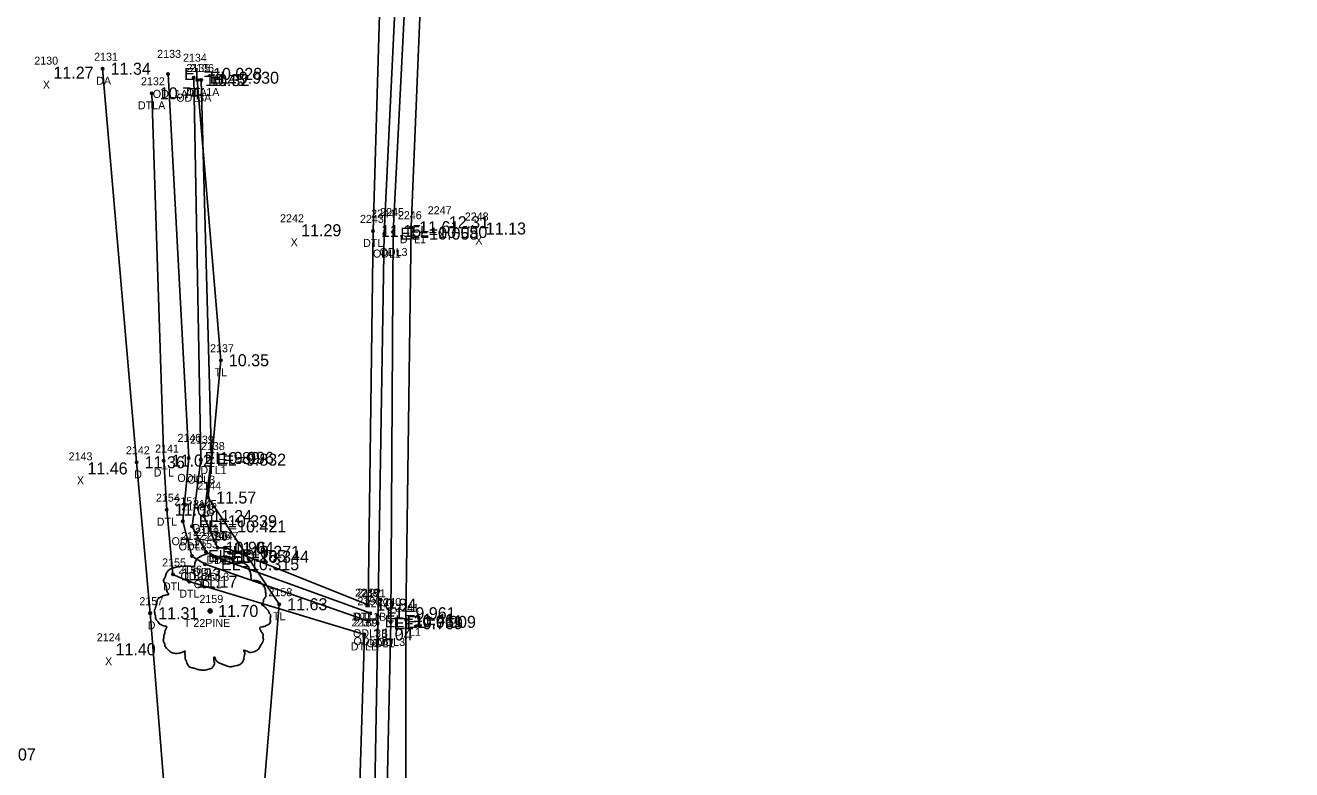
# Model space of a CAD drawing. Extents: x 2042117 to 2045853, y 303080 to 309569.
# Drawn here: x 2044366.1 to 2044524.3, y 304910.7 to 305003.7 of the extents above; entities that cross this region are included whole.
import ezdxf

# ---------------------------------------------------------------- set-up
doc = ezdxf.new("R2010")
doc.units = 0
for name, color, linetype in [('RD_EX_Driveway', 7, 'Continuous'), ('RD_EX_Driveway_txCode', 7, 'Continuous'), ('RD_EX_H2O', 7, 'Continuous'), ('RD_EX_H2O_txCode', 7, 'Continuous'), ('RD_EX_Misc_txCode', 7, 'Continuous'), ('RD_EX_TX_Driveway_ELEV', 7, 'Continuous'), ('RD_EX_TX_H2O_ELEV', 7, 'Continuous'), ('RD_EX_TX_Misc_ELEV', 7, 'Continuous'), ('RD_EX_TX_VEG_ELEV', 7, 'Continuous'), ('RD_EX_VEG', 7, 'Continuous'), ('RD_EX_VEG_txCode', 7, 'Continuous'), ('RD_SMD_Locator', 7, 'Continuous')]:
    doc.layers.add(name, color=color, linetype=linetype)

msp = doc.modelspace()

# ---------------------------------------------------------------- linework, layer by layer
at = {"layer": 'RD_EX_Driveway'}
msp.add_lwpolyline([(2044375.76, 304998.28), (2044380.01, 304949.11), (2044381.7, 304930.26), (2044386.83, 304866.36)], dxfattribs=at)
at = {"layer": 'RD_EX_H2O'}
for points in [[(2044403.47, 304870.69), (2044407.44, 304869.96), (2044408.86, 304871.35), (2044409.24, 304878.26), (2044410.13, 304929), (2044410.94, 304977.69), (2044415.72, 305077.93), (2044415.23, 305082.87), (2044413.63, 305085.18), (2044400.37, 305083.8), (2044376.8, 305083.33)], [(2044412.68, 304824.61), (2044412.4, 304834.83), (2044410.65, 304865.22), (2044410.04, 304868.77), (2044410.66, 304878.11), (2044411.75, 304929.17), (2044412.06, 304977.88), (2044417.16, 305077.8), (2044420.35, 305084.11), (2044441.54, 305085.32)], [(2044415.25, 304826.5), (2044414.68, 304834.74), (2044412.57, 304868.88), (2044413.59, 304878.38), (2044413.66, 304929.44), (2044414.3, 304978.48), (2044418.39, 305077.45), (2044423.01, 305082.15), (2044441.95, 305081.13)], [(2044408.92, 304931.32), (2044409.54, 304978.02), (2044412.44, 305076.31), (2044400.87, 305076.71), (2044383.06, 305073.87), (2044385, 305069.3)], [(2044383.93, 304997.64), (2044386.51, 304949.66), (2044385.78, 304941.75), (2044386.91, 304937.4), (2044388.55, 304936.38), (2044408.98, 304929.26)], [(2044387.15, 304997.16), (2044388.03, 304949.44), (2044386.94, 304941.1), (2044388.67, 304937.92), (2044389.77, 304937.31), (2044409.21, 304930.25)], [(2044388.07, 304996.86), (2044389.38, 304949.64), (2044388.41, 304942.4), (2044390.13, 304938.44), (2044391.11, 304938.42), (2044408.92, 304931.31)], [(2044381.9, 304995.21), (2044383.39, 304949.33), (2044383.77, 304943.19), (2044384.54, 304935.1), (2044386.58, 304934.2), (2044408.47, 304927.6)], [(2044410.56, 304822.99), (2044408.85, 304834.7), (2044407.58, 304865.58), (2044405.53, 304866.37), (2044405.23, 304866.22), (2044401.8, 304866.57), (2044399.35, 304868.17), (2044399.78, 304872.01), (2044401.54, 304873.59), (2044405.93, 304871.59), (2044407.19, 304871.81), (2044406.92, 304878.34), (2044408.47, 304927.6)]]:
    msp.add_lwpolyline(points, dxfattribs=at)
at = {"layer": 'RD_EX_VEG'}
msp.add_lwpolyline([(2044387.58, 304996.88), (2044390.53, 304961.86), (2044388.93, 304944.71), (2044397.82, 304931.38), (2044395.87, 304907.56), (2044407.42, 304883.17), (2044412.64, 304877.39), (2044413.34, 304846.91), (2044417.62, 304826.21), (2044417.53, 304827.99), (2044425.41, 304820.87), (2044430.68, 304811.06), (2044486.4, 304757.95), (2044546.53, 304677.07), (2044611.02, 304596.16), (2044662.5, 304521.9), (2044713.91, 304454.08), (2044725.96, 304441.86), (2044733.75, 304433.55)], dxfattribs=at)
for centre, radius in [((2044389.19, 304930.54), 0.25), ((2044389.18, 304930.52), 0.0001)]:
    msp.add_circle(centre, radius, dxfattribs=at)
for points in [[(2044389.32, 304937.71), (2044389.02, 304937.73), (2044388.7, 304937.63), (2044388.45, 304937.53), (2044388.23, 304937.46), (2044388, 304937.36), (2044387.7, 304937.18), (2044387.48, 304936.98), (2044387.35, 304936.73), (2044387.3, 304936.51), (2044387.25, 304936.23), (2044387.25, 304936.06), (2044387.13, 304936.03), (2044386.98, 304936.06), (2044386.73, 304936.13), (2044386.48, 304936.13), (2044386.23, 304936.13), (2044385.88, 304936.11), (2044385.53, 304936.11), (2044385.25, 304936.06), (2044384.93, 304936.01), (2044384.55, 304935.88), (2044384.2, 304935.76), (2044383.9, 304935.51), (2044383.65, 304935.03), (2044383.53, 304934.68), (2044383.38, 304934.44), (2044383.53, 304933.99), (2044383.7, 304933.64), (2044383.73, 304933.44), (2044383.8, 304933.01), (2044383.9, 304932.79), (2044384.03, 304932.59), (2044383.95, 304932.56), (2044383.58, 304932.51), (2044383.28, 304932.41), (2044382.85, 304932.19), (2044382.63, 304931.96), (2044382.53, 304931.64), (2044382.5, 304931.29), (2044382.4, 304931.09), (2044382.33, 304930.81), (2044382.3, 304930.74), (2044382.25, 304930.41), (2044382.35, 304929.96), (2044382.38, 304929.61), (2044382.5, 304929.39), (2044382.65, 304929.21), (2044382.83, 304928.96), (2044383.23, 304928.74), (2044383.55, 304928.64), (2044383.75, 304928.61), (2044383.58, 304928.11), (2044383.53, 304927.76), (2044383.4, 304927.36), (2044383.4, 304927.29), (2044383.35, 304926.81), (2044383.5, 304926.49), (2044383.58, 304926.11), (2044383.75, 304925.89), (2044384.03, 304925.59), (2044384.35, 304925.36), (2044384.85, 304925.24), (2044385.25, 304925.26), (2044385.83, 304925.44), (2044386.08, 304925.51), (2044386.05, 304925.34), (2044386.08, 304924.96), (2044386.08, 304924.54), (2044386.23, 304924.21), (2044386.33, 304923.94), (2044386.48, 304923.69), (2044386.8, 304923.46), (2044387.2, 304923.39), (2044387.63, 304923.24), (2044388.08, 304923.16), (2044388.58, 304923.14), (2044389.17, 304923.29), (2044389.45, 304923.41), (2044389.55, 304923.59), (2044389.75, 304923.96), (2044389.7, 304924.19), (2044389.72, 304924.79), (2044389.82, 304924.61), (2044390, 304924.26), (2044390.5, 304923.96), (2044390.9, 304923.79), (2044391.37, 304923.64), (2044391.67, 304923.56), (2044392.15, 304923.64), (2044392.52, 304923.71), (2044392.9, 304923.84), (2044393.2, 304924.11), (2044393.37, 304924.39), (2044393.42, 304924.66), (2044393.5, 304925.04), (2044393.55, 304925.21)], [(2044393.55, 304925.21), (2044393.47, 304925.39), (2044393.42, 304925.64), (2044393.5, 304925.61), (2044393.67, 304925.56), (2044393.95, 304925.44), (2044394.17, 304925.36), (2044394.5, 304925.39), (2044394.77, 304925.49), (2044395.22, 304925.76), (2044395.5, 304926.24), (2044395.77, 304926.64), (2044395.85, 304926.96), (2044395.8, 304927.19), (2044395.77, 304927.69), (2044395.57, 304927.94), (2044395.52, 304928.06), (2044395.42, 304928.46), (2044395.5, 304928.51), (2044395.77, 304928.56), (2044396.15, 304928.69), (2044396.42, 304928.81), (2044396.65, 304928.99), (2044396.72, 304929.21), (2044396.7, 304929.61), (2044396.75, 304930.01), (2044396.67, 304930.16), (2044396.57, 304930.31), (2044396.5, 304930.51), (2044396.35, 304930.66), (2044396.25, 304930.81), (2044396.15, 304930.91), (2044396.02, 304931.06), (2044395.85, 304931.19), (2044395.7, 304931.24), (2044395.65, 304931.39), (2044395.8, 304931.59), (2044395.85, 304931.69), (2044395.87, 304931.91), (2044396.1, 304932.26), (2044396.15, 304932.66), (2044396.1, 304933.09), (2044396.05, 304933.36), (2044395.9, 304933.64), (2044395.7, 304933.89), (2044395.57, 304934.06), (2044395.4, 304934.19), (2044395.07, 304934.31), (2044394.82, 304934.36), (2044394.47, 304934.36), (2044394.27, 304934.41), (2044394.3, 304934.46), (2044394.3, 304934.61), (2044394.3, 304934.88), (2044394.22, 304935.33), (2044394.07, 304935.83), (2044394.07, 304935.86), (2044393.97, 304936.11), (2044393.75, 304936.31), (2044393.57, 304936.41), (2044393.37, 304936.53), (2044393.12, 304936.56), (2044392.82, 304936.56), (2044392.55, 304936.51), (2044392.35, 304936.41), (2044392.17, 304936.28), (2044392.1, 304936.43), (2044392, 304936.73), (2044391.95, 304936.88), (2044391.8, 304937.06), (2044391.57, 304937.26), (2044391.12, 304937.38), (2044390.5, 304937.31), (2044390.2, 304937.11), (2044390.05, 304936.93), (2044390, 304937.06), (2044389.8, 304937.26), (2044389.7, 304937.43), (2044389.52, 304937.56), (2044389.37, 304937.66), (2044389.27, 304937.71)]]:
    msp.add_spline(points, degree=3, dxfattribs=at)
at = {"layer": 'RD_SMD_Locator'}
for centre in [(2044375.76, 304998.28), (2044383.93, 304997.64), (2044387.15, 304997.16), (2044387.58, 304996.88), (2044388.07, 304996.86), (2044381.9, 304995.21), (2044409.54, 304978.02), (2044410.94, 304977.69), (2044412.06, 304977.88), (2044414.3, 304978.48), (2044390.53, 304961.86), (2044380.01, 304949.11), (2044383.39, 304949.33), (2044386.51, 304949.66), (2044388.03, 304949.44), (2044389.38, 304949.64), (2044388.93, 304944.71), (2044383.77, 304943.19), (2044388.41, 304942.4), (2044385.78, 304941.75), (2044386.94, 304941.1), (2044388.67, 304937.92), (2044390.13, 304938.44), (2044391.11, 304938.42), (2044386.91, 304937.4), (2044388.55, 304936.38), (2044389.77, 304937.31), (2044384.54, 304935.1), (2044386.58, 304934.2), (2044397.82, 304931.38), (2044408.92, 304931.32), (2044408.92, 304931.31), (2044381.7, 304930.26), (2044389.19, 304930.54), (2044409.21, 304930.25), (2044408.98, 304929.26), (2044410.13, 304929), (2044411.75, 304929.17), (2044413.66, 304929.44), (2044408.47, 304927.6), (2044408.47, 304927.6)]:
    msp.add_circle(centre, 0.15, dxfattribs=at)

# ---------------------------------------------------------------- texts
at = {"layer": 'RD_EX_Driveway_txCode'}
for s, p in [('2131', (2044374.7, 304999.28)), ('DA', (2044374.96, 304996.28)), ('2142', (2044378.67, 304950.11)), ('D', (2044379.71, 304947.11)), ('2157', (2044380.35, 304931.26)), ('D', (2044381.39, 304928.26))]:
    msp.add_text(s, height=1, dxfattribs=at).set_placement(p)
at = {"layer": 'RD_EX_H2O_txCode'}
for s, p in [('2133', (2044382.58, 304999.64)), ('2134', (2044385.8, 304999.16)), ('2136', (2044386.7, 304997.86)), ('2132', (2044380.55, 304996.21)), ('ODL1A', (2044382.03, 304994.64)), ('ODL3A', (2044384.96, 304994.16)), ('DTL1A', (2044386.18, 304994.86)), ('DTLA', (2044380.17, 304993.21)), ('2244', (2044409.31, 304979.69)), ('2245', (2044410.43, 304979.88)), ('2246', (2044412.65, 304979.48)), ('2243', (2044407.91, 304979.02)), ('DTL1', (2044412.89, 304976.48)), ('DTL', (2044408.3, 304976.02)), ('ODL1', (2044409.53, 304974.69)), ('ODL3', (2044410.36, 304974.88)), ('2140', (2044385.12, 304951.66)), ('2139', (2044386.68, 304951.44)), ('2141', (2044382.32, 304950.33)), ('2138', (2044388.04, 304950.64)), ('DTL', (2044382.14, 304947.33)), ('ODL1', (2044385.1, 304946.66)), ('ODL3', (2044386.33, 304946.44)), ('DTL1', (2044387.97, 304947.64)), ('2154', (2044382.42, 304944.19)), ('2151', (2044384.72, 304943.75)), ('2148', (2044385.59, 304943.1)), ('2145', (2044387.06, 304943.4)), ('DTL', (2044382.52, 304941.19)), ('DTL1', (2044387, 304940.4)), ('2149', (2044387.32, 304939.92)), ('ODL1', (2044384.37, 304938.75)), ('2152', (2044385.57, 304939.4)), ('2153', (2044387.2, 304938.38)), ('2150', (2044388.39, 304939.31)), ('2146', (2044388.76, 304939.44)), ('2147', (2044389.76, 304939.42)), ('ODL3', (2044385.25, 304938.1)), ('2155', (2044383.2, 304936.1)), ('2156', (2044385.21, 304935.2)), ('DTL1', (2044388.72, 304936.44)), ('DTL1', (2044389.7, 304936.42)), ('ODL1', (2044385.5, 304934.4)), ('ODL3', (2044386.97, 304934.92)), ('ODL3', (2044388.08, 304934.31)), ('DTL', (2044383.3, 304933.1)), ('DTL', (2044385.34, 304932.2)), ('ODL1', (2044387.14, 304933.38)), ('2238', (2044407.29, 304932.32)), ('2192', (2044407.57, 304932.31)), ('2191', (2044408.15, 304932.25)), ('2190', (2044407.59, 304931.26)), ('2239', (2044408.5, 304931)), ('2240', (2044410.08, 304931.17)), ('2241', (2044412.32, 304930.44)), ('DTL1B', (2044407.03, 304929.31)), ('DTLA', (2044407.18, 304929.32)), ('2237', (2044406.84, 304928.6)), ('ODL3B', (2044407.04, 304927.25)), ('2189', (2044407.13, 304928.6)), ('DTL1', (2044412.25, 304927.44)), ('DTLB', (2044406.76, 304925.6)), ('DTLB', (2044406.76, 304925.6)), ('ODL1B', (2044407.1, 304926.26)), ('ODL1', (2044408.72, 304926)), ('ODL3', (2044410.06, 304926.17))]:
    msp.add_text(s, height=1, dxfattribs=at).set_placement(p)
at = {"layer": 'RD_EX_Misc_txCode'}
for s, p in [('2130', (2044367.22, 304998.79)), ('X', (2044368.29, 304995.79)), ('2247', (2044416.38, 304980.1)), ('2248', (2044421, 304979.32)), ('2242', (2044397.93, 304979.1)), ('X', (2044417.7, 304977.1)), ('X', (2044422.32, 304976.32)), ('X', (2044399.25, 304976.1)), ('2143', (2044371.51, 304949.35)), ('X', (2044372.55, 304946.35)), ('2124', (2044375.03, 304926.75)), ('X', (2044376.06, 304923.75))]:
    msp.add_text(s, height=1, dxfattribs=at).set_placement(p)
at = {"layer": 'RD_EX_TX_Driveway_ELEV'}
for s, p in [('11.34', (2044376.76, 304997.53)), ('11.36', (2044381.01, 304948.36)), ('11.31', (2044382.7, 304929.51)), ('11.07', (2044362.39, 304911.86))]:
    msp.add_text(s, height=1.5, dxfattribs=at).set_placement(p)
at = {"layer": 'RD_EX_TX_H2O_ELEV'}
for s, p in [('EL=10.028', (2044385.93, 304996.89)), ('EL=9.930', (2044389.15, 304996.41)), ('10.32', (2044389.07, 304996.11)), ('10.74', (2044382.9, 304994.46)), ('11.15', (2044410.54, 304977.27)), ('11.61', (2044415.3, 304977.73)), ('EL=10.058', (2044412.94, 304976.94)), ('EL=10.050', (2044414.06, 304977.13)), ('EL=9.996', (2044388.51, 304948.91)), ('10.89', (2044390.38, 304948.89)), ('11.02', (2044384.39, 304948.58)), ('EL=9.832', (2044390.03, 304948.69)), ('11.08', (2044384.77, 304942.44)), ('EL=10.339', (2044387.78, 304941)), ('11.24', (2044389.41, 304941.65)), ('EL=10.421', (2044388.94, 304940.35)), ('10.96', (2044391.13, 304937.69)), ('11.04', (2044392.11, 304937.67)), ('EL=10.285', (2044388.91, 304936.65)), ('EL=10.271', (2044390.67, 304937.17)), ('EL=10.344', (2044391.77, 304936.56)), ('EL=10.315', (2044390.55, 304935.63)), ('11.23', (2044385.54, 304934.35)), ('11.17', (2044387.58, 304933.45)), ('10.84', (2044409.92, 304930.56)), ('10.84', (2044409.92, 304930.57)), ('EL=10.061', (2044410.98, 304928.51)), ('EL=9.961', (2044411.21, 304929.5)), ('EL=9.769', (2044412.13, 304928.25)), ('EL=9.909', (2044413.75, 304928.42)), ('11.41', (2044414.66, 304928.69)), ('11.04', (2044409.47, 304926.85)), ('11.04', (2044409.47, 304926.85))]:
    msp.add_text(s, height=1.5, dxfattribs=at).set_placement(p)
at = {"layer": 'RD_EX_TX_Misc_ELEV'}
for s, p in [('11.27', (2044369.61, 304997.04)), ('11.29', (2044400.56, 304977.35)), ('12.31', (2044419.01, 304978.35)), ('11.13', (2044423.63, 304977.57)), ('11.46', (2044373.86, 304947.6)), ('11.40', (2044377.37, 304925))]:
    msp.add_text(s, height=1.5, dxfattribs=at).set_placement(p)
at = {"layer": 'RD_EX_TX_VEG_ELEV'}
for s, p in [('10.45', (2044388.58, 304996.13)), ('10.35', (2044391.53, 304961.11)), ('11.57', (2044389.93, 304943.96)), ('11.70', (2044390.19, 304929.79)), ('11.63', (2044398.82, 304930.63))]:
    msp.add_text(s, height=1.5, dxfattribs=at).set_placement(p)
at = {"layer": 'RD_EX_VEG_txCode'}
for s, p in [('2135', (2044386.23, 304997.88)), ('TLA', (2044386.32, 304994.88)), ('2137', (2044389.18, 304962.86)), ('TL', (2044389.76, 304959.86)), ('2144', (2044387.59, 304945.71)), ('TL', (2044388.16, 304942.71)), ('2158', (2044396.48, 304932.38)), ('2159', (2044387.85, 304931.54)), ('TL', (2044397.05, 304929.38)), ('T 22PINE', (2044385.91, 304928.54))]:
    msp.add_text(s, height=1, dxfattribs=at).set_placement(p)

doc.saveas('drawing.dxf')
